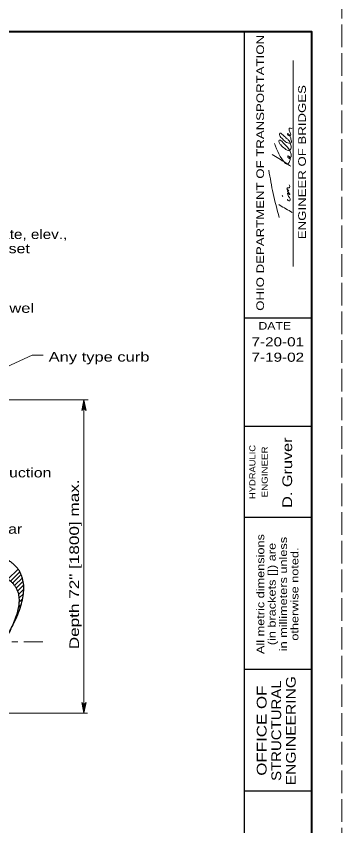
# Model space of a CAD drawing. Extents: x 1083.1 to 1117.1, y 719.4 to 763.4.
# Drawn here: x 1111.77 to 1117.13, y 727.78 to 741.1 of the extents above; entities that cross this region are included whole.
import ezdxf
from ezdxf.enums import TextEntityAlignment as Align

# ---------------------------------------------------------------- set-up
doc = ezdxf.new("R2010")
doc.units = 0
doc.header["$LTSCALE"] = 0.062
doc.linetypes.add('DOT_DASHED', pattern=[7.7, 5, -1.2, 0.3, -1.2])
doc.linetypes.add('LONG_DASHED', pattern=[7.5, 6, -1.5])
doc.layers.add('1', color=7, linetype='Continuous', lineweight=13)

msp = doc.modelspace()

# ---------------------------------------------------------------- linework, layer by layer
at = {"layer": '1', "lineweight": 25}
for p, q in [((1085.12642, 740.85408), (1116.62642, 740.85408)), ((1115.52642, 719.85408), (1115.52642, 740.85408)), ((1116.62642, 740.85408), (1116.62642, 719.85408)), ((1116.62642, 736.13825), (1115.52642, 736.13825)), ((1116.62642, 734.35408), (1115.52642, 734.35408)), ((1116.62642, 732.85408), (1115.52642, 732.85408)), ((1116.62642, 730.35408), (1115.52642, 730.35408)), ((1116.62642, 728.35408), (1115.52642, 728.35408))]:
    msp.add_line(p, q, dxfattribs=at)
at = {"layer": '1'}
for p, q in [((1116.32517, 736.98508), (1116.32517, 740.37517)), ((1116.15767, 738.136), (1116.1475, 738.15525)), ((1110.82092, 734.97183), (1112.03292, 735.52567)), ((1112.03292, 735.52567), (1112.21417, 735.52567)), ((1112.95483, 734.79242), (1109.78875, 734.79242)), ((1112.85767, 734.63025), (1112.88242, 734.79242)), ((1112.868, 734.63633), (1112.88242, 734.79242)), ((1112.88242, 734.63917), (1112.88242, 734.79242)), ((1112.89375, 734.6375), (1112.88242, 734.79242)), ((1112.90483, 734.63208), (1112.88242, 734.79242)), ((1112.88242, 734.79242), (1112.88242, 729.63575)), ((1111.63333, 731.84), (1111.80042, 732.00708)), ((1111.674, 731.80992), (1111.82817, 731.96408)), ((1111.71058, 731.77592), (1111.85158, 731.91683)), ((1111.74258, 731.73725), (1111.8705, 731.865)), ((1111.76967, 731.69367), (1111.88417, 731.80808)), ((1111.79125, 731.6445), (1111.89225, 731.74542)), ((1111.8065, 731.589), (1111.89383, 731.67633)), ((1111.81467, 731.52642), (1111.88833, 731.60008)), ((1111.8145, 731.45558), (1111.87458, 731.51567)), ((1111.80467, 731.375), (1111.85117, 731.42158)), ((1111.78317, 731.28275), (1111.81667, 731.31633)), ((1112.86, 729.79608), (1112.88242, 729.63575)), ((1112.87108, 729.79067), (1112.88242, 729.63575)), ((1112.90725, 729.798), (1112.88242, 729.63575)), ((1112.89683, 729.79183), (1112.88242, 729.63575)), ((1112.88242, 729.789), (1112.88242, 729.63575)), ((1111.53233, 729.63575), (1112.9445, 729.63575))]:
    msp.add_line(p, q, dxfattribs=at)
at = {"layer": '1', "linetype": 'DOT_DASHED'}
msp.add_line((1109.45583, 730.81133), (1112.25767, 730.81133), dxfattribs=at)
at = {"layer": '1', "linetype": 'LONG_DASHED'}
msp.add_lwpolyline([(1083.12642, 719.35408), (1117.12642, 719.35408), (1117.12642, 741.35408), (1083.12642, 741.35408)], close=True, dxfattribs=at)
at = {"layer": '1', "lineweight": 40}
msp.add_lwpolyline([(1085.12642, 740.85408), (1116.62642, 740.85408), (1116.62642, 719.85408), (1085.12642, 719.85408)], close=True, dxfattribs=at)
msp.add_lwpolyline([(1085.12642, 740.85408), (1116.62642, 740.85408), (1116.62642, 719.85408), (1085.12642, 719.85408)], close=True, dxfattribs=at)
at = {"layer": '1'}
for points in [[(1112.847, 734.61533), (1112.88242, 734.79242), (1112.91783, 734.61533)], [(1112.91783, 729.81283), (1112.88242, 729.63575), (1112.847, 729.81283)]]:
    msp.add_lwpolyline(points, dxfattribs=at)
for centre, start, end in [((1112.88248, 734.60104), 22.08782, 157.91395), ((1112.8824, 729.82716), 202.08782, 337.91395)]:
    msp.add_arc(centre, 0.03822, start, end, dxfattribs=at)
for points in [[(1116.01825, 739.01108), (1116.20142, 738.68275), (1116.21658, 738.67217), (1116.22675, 738.67217), (1116.25867, 738.69583), (1116.27375, 738.73), (1116.26875, 738.78125), (1116.25183, 738.80308), (1116.23833, 738.80308), (1116.23658, 738.79008), (1116.24675, 738.77492), (1116.26025, 738.7665), (1116.27533, 738.7665), (1116.2905, 738.78808), (1116.29392, 738.80742), (1116.28367, 738.86275), (1116.20142, 738.98317), (1116.15592, 739.02783), (1116.119, 739.06242), (1116.09383, 739.06458), (1116.09558, 739.026), (1116.12075, 738.98725), (1116.188, 738.92492), (1116.23008, 738.8995), (1116.26375, 738.895), (1116.28708, 738.921), (1116.29392, 738.95517), (1116.28883, 738.98092), (1116.25867, 739.05408), (1116.22842, 739.08608), (1116.16783, 739.1395), (1116.13917, 739.16533), (1116.10567, 739.18058), (1116.10225, 739.15258), (1116.11233, 739.12675), (1116.1695, 739.06683), (1116.24017, 739.01958), (1116.29217, 739.02192), (1116.2905, 739.07958), (1116.27867, 739.1225), (1116.26533, 739.14825), (1116.25517, 739.159), (1116.23175, 739.174), (1116.2335, 739.15692), (1116.26875, 739.13542), (1116.28367, 739.14617), (1116.27058, 739.19983), (1116.262, 739.22775), (1116.25867, 739.24042), (1116.25867, 739.25325), (1116.25867, 739.26192), (1116.28367, 739.25975), (1116.30908, 739.25975)], [(1115.97942, 738.82883), (1116.20317, 738.69133), (1116.28883, 738.63567)], [(1116.09567, 737.79183), (1115.997, 738.18708), (1115.92575, 738.56942)], [(1116.22675, 738.09075), (1116.235, 738.08008), (1116.27217, 738.06717), (1116.27692, 738.09958), (1116.25183, 738.136), (1116.23658, 738.17225), (1116.23658, 738.1915), (1116.25183, 738.18525), (1116.262, 738.17442), (1116.27217, 738.17008), (1116.2485, 738.20225), (1116.23658, 738.21725), (1116.2335, 738.23458), (1116.25692, 738.228), (1116.2485, 738.23667), (1116.22333, 738.2645), (1116.2335, 738.27967), (1116.25025, 738.28167), (1116.25867, 738.27967), (1116.26875, 738.301), (1116.262, 738.32892)], [(1116.31083, 737.87625), (1116.10567, 737.99625), (1116.09008, 738.00667)]]:
    msp.add_spline(points, degree=3, dxfattribs=at)
at = {"layer": '1', "lineweight": 25}
for points in [[(1111.53233, 730.7645), (1112.25583, 731.904), (1111.53233, 732.20567)], [(1111.53233, 731.89317), (1112.099, 731.657), (1111.53233, 730.7645)]]:
    msp.add_open_spline(points, degree=2, dxfattribs=at)

# ---------------------------------------------------------------- texts
at = {"layer": '1'}
for s, height, width, p in [('OHIO DEPARTMENT OF TRANSPORTATION', 0.125, 1.3, (1115.84633, 738.52633)), ('ENGINEER OF BRIDGES', 0.125, 1.3, (1116.53467, 738.70312)), ('D. Gruver', 0.16, 1.25, (1116.30875, 733.59333)), ('HYDRAULIC', 0.1, 1.15, (1115.7055, 733.60517)), ('ENGINEER', 0.1, 1.2, (1115.90642, 733.60521)), ('All metric dimensions', 0.125, 1.25, (1115.85025, 731.59617)), ('in millimeters unless', 0.125, 1.25, (1116.22525, 731.59621)), ('(in brackets []) are', 0.125, 1.25, (1116.03775, 731.59617)), ('otherwise noted.', 0.125, 1.25, (1116.41275, 731.59617)), ('STRUCTURAL', 0.16, 1.15, (1116.12817, 729.34854)), ('ENGINEERING', 0.16, 1.2, (1116.36817, 729.34862)), ('OFFICE OF', 0.16, 1.3, (1115.88817, 729.34854))]:
    msp.add_text(s, height=height, rotation=90, dxfattribs=dict(at, width=width)).set_placement(p, align=Align.CENTER)
for s, width, p in [('Location of grate, elev.,', 1.2, (1110.00683, 737.43833)), ('station and offset', 1.25, (1110.00683, 737.20367)), ('1" [25] Dowel', 1.3, (1110.45975, 736.22333)), ('Any type curb', 1.3, (1112.30367, 735.42133)), ('Construction', 1.25, (1110.8845, 733.5155)), ('Mortar', 1.25, (1111.11475, 732.58883))]:
    msp.add_text(s, height=0.156, dxfattribs=dict(at, width=width)).set_placement(p)
for s, height, width, p in [('DATE', 0.125, 1.2, (1116.02312, 735.94683)), ('7-20-01', 0.15, 1.25, (1116.07346, 735.67133)), ('7-19-02', 0.15, 1.25, (1116.07346, 735.41825))]:
    msp.add_text(s, height=height, dxfattribs=dict(at, width=width)).set_placement(p, align=Align.CENTER)
at = {"layer": '1', "width": 1.35}
msp.add_text('Depth 72" [1800] max.', height=0.156, rotation=90, dxfattribs=at).set_placement((1112.80175, 730.68875))

doc.saveas('drawing.dxf')
